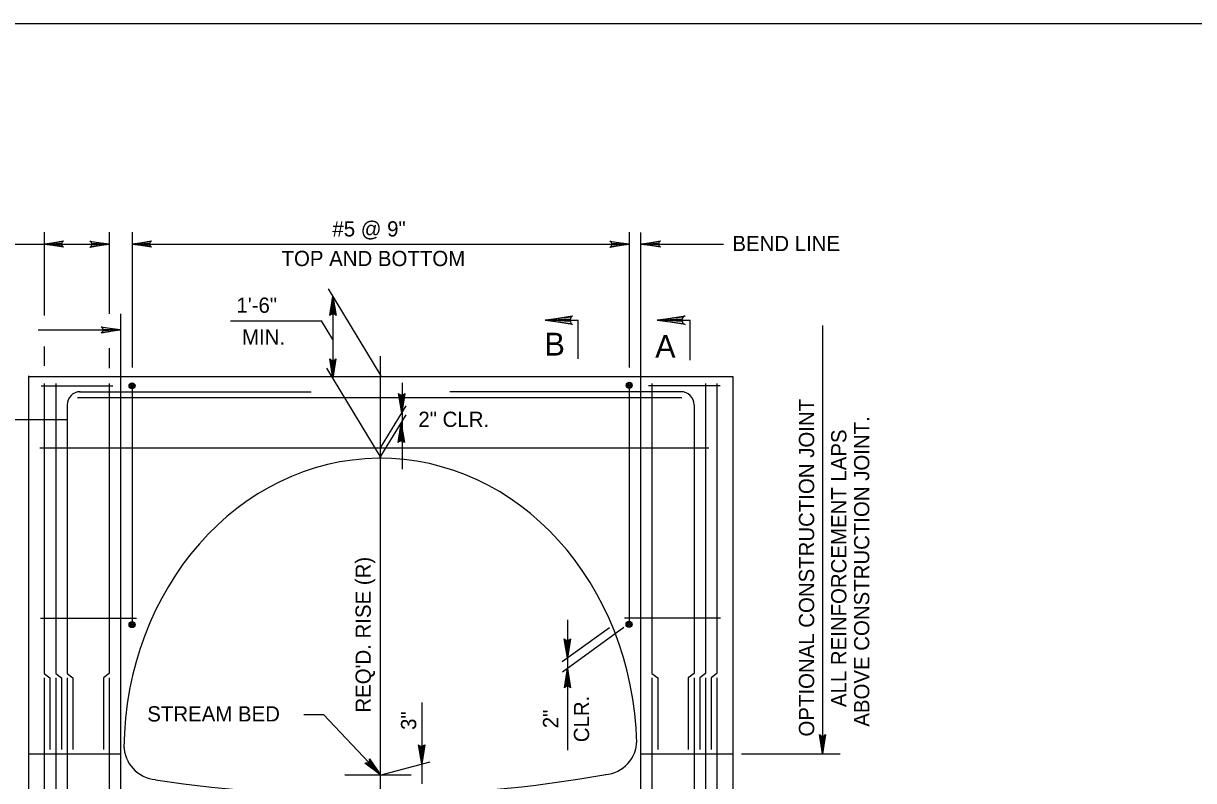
# Model space of a CAD drawing. Extents: x 639011 to 639866, y 298840 to 300028.
# Drawn here: x 639168.1 to 639398.1, y 299269.9 to 299418.8 of the extents above; entities that cross this region are included whole.
import ezdxf

# ---------------------------------------------------------------- set-up
doc = ezdxf.new("R2010")
doc.units = 0
doc.layers.add('2', color=7, linetype='Continuous')

msp = doc.modelspace()

# ---------------------------------------------------------------- linework, layer by layer
at = {"layer": '2'}
for p, q in [((639051.26, 299418.83), (639837.26, 299418.83)), ((639172.17, 299377.76), (639172.17, 299361.38)), ((639184.93, 299377.76), (639184.93, 299361.72)), ((639189.43, 299377.76), (639189.43, 299351.14)), ((639287.15, 299377.76), (639287.15, 299351.14)), ((639289.4, 299377.71), (639289.4, 299238.79)), ((639166.21, 299375.41), (639184.93, 299375.41)), ((639172.17, 299375.41), (639175.96, 299376.04)), ((639175.77, 299375.87), (639172.17, 299375.41)), ((639172.17, 299375.41), (639175.64, 299375.6)), ((639172.17, 299375.41), (639175.64, 299375.42)), ((639175.64, 299375.24), (639172.17, 299375.41)), ((639172.17, 299375.41), (639175.78, 299374.98)), ((639175.97, 299374.82), (639172.17, 299375.41)), ((639175.64, 299375.6), (639175.77, 299375.87)), ((639175.64, 299375.24), (639175.64, 299375.6)), ((639175.78, 299374.98), (639175.64, 299375.24)), ((639175.96, 299376.04), (639175.77, 299375.87)), ((639175.78, 299374.98), (639175.97, 299374.82)), ((639181.32, 299375.84), (639181.13, 299376)), ((639181.13, 299376), (639184.93, 299375.41)), ((639184.93, 299375.41), (639181.14, 299374.77)), ((639181.14, 299374.77), (639181.33, 299374.95)), ((639181.32, 299375.84), (639181.46, 299375.57)), ((639184.93, 299375.41), (639181.32, 299375.84)), ((639181.33, 299374.95), (639184.93, 299375.41)), ((639181.46, 299375.21), (639181.33, 299374.95)), ((639181.46, 299375.57), (639184.93, 299375.41)), ((639181.46, 299375.57), (639181.46, 299375.21)), ((639184.93, 299375.41), (639181.46, 299375.21)), ((639184.93, 299375.41), (639181.46, 299375.39)), ((639189.43, 299375.41), (639193.22, 299376.04)), ((639193.03, 299375.87), (639189.43, 299375.41)), ((639189.43, 299375.41), (639192.9, 299375.6)), ((639189.43, 299375.41), (639192.9, 299375.42)), ((639189.43, 299375.41), (639287.15, 299375.41)), ((639192.9, 299375.24), (639189.43, 299375.41)), ((639189.43, 299375.41), (639193.04, 299374.98)), ((639193.23, 299374.82), (639189.43, 299375.41)), ((639192.9, 299375.6), (639193.03, 299375.87)), ((639192.9, 299375.24), (639192.9, 299375.6)), ((639193.04, 299374.98), (639192.9, 299375.24)), ((639193.22, 299376.04), (639193.03, 299375.87)), ((639193.04, 299374.98), (639193.23, 299374.82)), ((639283.54, 299375.84), (639283.35, 299376)), ((639283.35, 299376), (639287.15, 299375.41)), ((639287.15, 299375.41), (639283.36, 299374.77)), ((639283.36, 299374.77), (639283.55, 299374.95)), ((639283.54, 299375.84), (639283.68, 299375.57)), ((639287.15, 299375.41), (639283.54, 299375.84)), ((639283.55, 299374.95), (639287.15, 299375.41)), ((639283.68, 299375.21), (639283.55, 299374.95)), ((639283.68, 299375.57), (639287.15, 299375.41)), ((639283.68, 299375.57), (639283.68, 299375.21)), ((639287.15, 299375.41), (639283.68, 299375.21)), ((639287.15, 299375.41), (639283.68, 299375.39)), ((639289.54, 299375.42), (639293.34, 299376.05)), ((639293.14, 299375.88), (639289.54, 299375.42)), ((639289.54, 299375.42), (639293.01, 299375.61)), ((639289.54, 299375.42), (639293.02, 299375.43)), ((639289.54, 299375.42), (639305.74, 299375.42)), ((639293.02, 299375.25), (639289.54, 299375.42)), ((639289.54, 299375.42), (639293.15, 299374.99)), ((639293.34, 299374.83), (639289.54, 299375.42)), ((639293.01, 299375.61), (639293.14, 299375.88)), ((639293.02, 299375.25), (639293.01, 299375.61)), ((639293.15, 299374.99), (639293.02, 299375.25)), ((639293.34, 299376.05), (639293.14, 299375.88)), ((639293.15, 299374.99), (639293.34, 299374.83)), ((639238.42, 299349.51), (639228.02, 299366.65)), ((639228.34, 299361.35), (639228.93, 299365.16)), ((639228.93, 299365.16), (639228.5, 299361.55)), ((639228.76, 299361.68), (639228.93, 299365.16)), ((639228.93, 299365.16), (639228.93, 299349.03)), ((639228.93, 299365.16), (639229.13, 299361.68)), ((639229.39, 299361.56), (639228.93, 299365.16)), ((639228.93, 299365.16), (639229.57, 299361.36)), ((639228.93, 299365.16), (639228.95, 299361.68)), ((639187.18, 299361.72), (639187.18, 299238.5)), ((639228.5, 299361.55), (639228.34, 299361.35)), ((639228.5, 299361.55), (639228.76, 299361.68)), ((639228.76, 299361.68), (639229.13, 299361.68)), ((639229.13, 299361.68), (639229.39, 299361.56)), ((639229.57, 299361.36), (639229.39, 299361.56)), ((639170.98, 299358.55), (639187.18, 299358.55)), ((639183.57, 299358.98), (639183.38, 299359.14)), ((639183.38, 299359.14), (639187.18, 299358.55)), ((639187.18, 299358.55), (639183.39, 299357.91)), ((639183.57, 299358.98), (639183.71, 299358.71)), ((639187.18, 299358.55), (639183.57, 299358.98)), ((639183.58, 299358.09), (639187.18, 299358.55)), ((639183.71, 299358.71), (639187.18, 299358.55)), ((639183.71, 299358.71), (639183.71, 299358.35)), ((639187.18, 299358.55), (639183.71, 299358.35)), ((639187.18, 299358.55), (639183.71, 299358.53)), ((639208.76, 299360.34), (639226.67, 299360.34)), ((639228.93, 299356.62), (639226.67, 299360.34)), ((639270.67, 299360.44), (639277.17, 299360.44)), ((639270.67, 299360.44), (639277.17, 299360.44)), ((639277.17, 299352.82), (639277.17, 299360.44)), ((639292.67, 299360.44), (639299.17, 299360.44)), ((639292.67, 299360.44), (639299.17, 299360.44)), ((639299.17, 299352.59), (639299.17, 299360.44)), ((639299.17, 299355.82), (639299.17, 299360.44)), ((639325.2, 299359.41), (639325.2, 299275.13)), ((639183.39, 299357.91), (639183.58, 299358.09)), ((639183.71, 299358.35), (639183.58, 299358.09)), ((639172.17, 299355.29), (639172.17, 299351.44)), ((639184.93, 299354.96), (639184.93, 299351.04)), ((639228.93, 299349.03), (639228.3, 299352.83)), ((639228.3, 299352.83), (639228.47, 299352.63)), ((639228.73, 299352.5), (639228.47, 299352.63)), ((639228.47, 299352.63), (639228.93, 299349.03)), ((639228.93, 299349.03), (639228.73, 299352.5)), ((639229.1, 299352.5), (639228.73, 299352.5)), ((639228.93, 299349.03), (639228.92, 299352.5)), ((639229.52, 299352.83), (639228.93, 299349.03)), ((639228.93, 299349.03), (639229.36, 299352.64)), ((639229.1, 299352.5), (639228.93, 299349.03)), ((639229.36, 299352.64), (639229.1, 299352.5)), ((639229.36, 299352.64), (639229.52, 299352.83)), ((639238.29, 299211.29), (639238.29, 299353.37)), ((639169.04, 299349.51), (639169.04, 299242.01)), ((639169.04, 299349.38), (639187.18, 299349.38)), ((639187.18, 299349.38), (639289.4, 299349.38)), ((639238.42, 299333.38), (639227.71, 299351.04)), ((639289.4, 299349.38), (639307.54, 299349.38)), ((639307.54, 299349.38), (639307.54, 299265.13)), ((639171.56, 299347.51), (639185.64, 299347.51)), ((639172.17, 299348), (639172.17, 299290.98)), ((639174.42, 299348), (639174.42, 299290.98)), ((639184.93, 299348.02), (639184.93, 299290.98)), ((639189.43, 299347.04), (639189.43, 299301.19)), ((639242.51, 299348.16), (639242.51, 299331.12)), ((639287.15, 299347.04), (639287.15, 299301.19)), ((639305.03, 299347.51), (639290.94, 299347.51)), ((639291.65, 299348.02), (639291.65, 299290.98)), ((639302.17, 299348), (639302.17, 299290.98)), ((639304.42, 299348), (639304.42, 299290.98)), ((639178.73, 299345.26), (639297.54, 299345.26)), ((639179.11, 299346.38), (639224.65, 299346.38)), ((639242.46, 299342.21), (639241.83, 299346)), ((639241.83, 299346), (639242, 299345.81)), ((639242.27, 299345.68), (639242, 299345.81)), ((639242, 299345.81), (639242.46, 299342.21)), ((639242.46, 299342.21), (639242.27, 299345.68)), ((639242.63, 299345.68), (639242.27, 299345.68)), ((639242.46, 299342.21), (639242.45, 299345.68)), ((639243.05, 299346.01), (639242.46, 299342.21)), ((639242.46, 299342.21), (639242.89, 299345.82)), ((639242.63, 299345.68), (639242.46, 299342.21)), ((639242.89, 299345.82), (639242.63, 299345.68)), ((639242.89, 299345.82), (639243.05, 299346.01)), ((639297.47, 299346.38), (639251.91, 299346.38)), ((639176.67, 299343.8), (639176.67, 299290.98)), ((639238.29, 299335.37), (639243.3, 299343.62)), ((639299.92, 299343.8), (639299.92, 299290.98)), ((639176.52, 299340.83), (639154.57, 299340.83)), ((639238.17, 299333.38), (639243.31, 299341.86)), ((639241.76, 299336.41), (639242.35, 299340.22)), ((639242.35, 299340.22), (639241.92, 299336.61)), ((639242.19, 299336.74), (639242.35, 299340.22)), ((639242.35, 299340.22), (639242.55, 299336.75)), ((639242.81, 299336.62), (639242.35, 299340.22)), ((639242.35, 299340.22), (639242.99, 299336.42)), ((639242.35, 299340.22), (639242.37, 299336.74)), ((639171.28, 299335.37), (639302.83, 299335.37)), ((639241.92, 299336.61), (639241.76, 299336.41)), ((639241.92, 299336.61), (639242.19, 299336.74)), ((639242.19, 299336.74), (639242.55, 299336.75)), ((639242.55, 299336.75), (639242.81, 299336.62)), ((639242.99, 299336.42), (639242.81, 299336.62)), ((639171.43, 299301.83), (639190.31, 299301.83)), ((639275.02, 299301.49), (639275.02, 299293.97)), ((639305.15, 299301.83), (639286.27, 299301.83)), ((639283.28, 299299.94), (639274.02, 299293.23)), ((639286.15, 299299.98), (639274.05, 299291.2)), ((639275.02, 299293.97), (639274.39, 299297.77)), ((639274.39, 299297.77), (639274.56, 299297.57)), ((639274.82, 299297.45), (639274.56, 299297.57)), ((639274.56, 299297.57), (639275.02, 299293.97)), ((639275.02, 299293.97), (639274.82, 299297.45)), ((639275.19, 299297.45), (639274.82, 299297.45)), ((639275.02, 299293.97), (639275, 299297.45)), ((639275.61, 299297.78), (639275.02, 299293.97)), ((639275.02, 299293.97), (639275.45, 299297.58)), ((639275.19, 299297.45), (639275.02, 299293.97)), ((639275.45, 299297.58), (639275.19, 299297.45)), ((639275.45, 299297.58), (639275.61, 299297.78)), ((639275.02, 299293.97), (639275.02, 299291.94)), ((639274.43, 299288.14), (639275.02, 299291.94)), ((639275.02, 299291.94), (639274.59, 299288.33)), ((639274.85, 299288.47), (639275.02, 299291.94)), ((639275.02, 299291.94), (639275.02, 299275.87)), ((639275.02, 299291.94), (639275.22, 299288.47)), ((639275.48, 299288.34), (639275.02, 299291.94)), ((639275.02, 299291.94), (639275.65, 299288.15)), ((639275.02, 299291.94), (639275.03, 299288.47)), ((639172.17, 299290.98), (639173.29, 299290.11)), ((639172.17, 299290.11), (639172.17, 299243.37)), ((639173.29, 299290.11), (639173.29, 299275.98)), ((639174.42, 299290.98), (639175.54, 299290.11)), ((639174.42, 299290.11), (639174.42, 299243.37)), ((639175.54, 299290.11), (639175.54, 299275.98)), ((639176.67, 299290.98), (639177.79, 299290.11)), ((639176.67, 299290.11), (639176.67, 299247.73)), ((639177.79, 299290.11), (639177.79, 299275.98)), ((639184.93, 299290.98), (639183.81, 299290.11)), ((639183.81, 299290.11), (639183.81, 299275.98)), ((639184.93, 299290.11), (639184.93, 299243.56)), ((639291.65, 299290.98), (639292.78, 299290.11)), ((639291.65, 299290.11), (639291.65, 299243.56)), ((639292.78, 299290.11), (639292.78, 299275.98)), ((639299.92, 299290.98), (639298.79, 299290.11)), ((639298.79, 299290.11), (639298.79, 299275.98)), ((639299.92, 299290.11), (639299.92, 299247.72)), ((639302.17, 299290.98), (639301.04, 299290.11)), ((639301.04, 299290.11), (639301.04, 299275.98)), ((639302.17, 299290.11), (639302.17, 299243.37)), ((639304.42, 299290.98), (639303.29, 299290.11)), ((639303.29, 299290.11), (639303.29, 299275.98)), ((639304.42, 299290.11), (639304.42, 299243.37)), ((639274.59, 299288.33), (639274.43, 299288.14)), ((639274.59, 299288.33), (639274.85, 299288.47)), ((639274.85, 299288.47), (639275.22, 299288.47)), ((639275.22, 299288.47), (639275.48, 299288.34)), ((639275.65, 299288.15), (639275.48, 299288.34)), ((639246.38, 299285.23), (639246.38, 299273.15)), ((639223.17, 299282.88), (639227.04, 299282.88)), ((639227.04, 299282.88), (639238.29, 299271.01)), ((639325.2, 299275.13), (639324.57, 299278.93)), ((639324.57, 299278.93), (639324.75, 299278.73)), ((639325.01, 299278.6), (639324.75, 299278.73)), ((639324.75, 299278.73), (639325.2, 299275.13)), ((639325.37, 299278.61), (639325.01, 299278.6)), ((639325.2, 299275.13), (639325.01, 299278.6)), ((639325.2, 299275.13), (639325.19, 299278.6)), ((639325.79, 299278.93), (639325.2, 299275.13)), ((639325.2, 299275.13), (639325.63, 299278.74)), ((639325.37, 299278.61), (639325.2, 299275.13)), ((639325.63, 299278.74), (639325.37, 299278.61)), ((639325.63, 299278.74), (639325.79, 299278.93)), ((639246.38, 299273.15), (639245.75, 299276.94)), ((639245.75, 299276.94), (639245.92, 299276.74)), ((639246.18, 299276.62), (639245.92, 299276.74)), ((639245.92, 299276.74), (639246.38, 299273.15)), ((639246.38, 299273.15), (639246.18, 299276.62)), ((639246.55, 299276.62), (639246.18, 299276.62)), ((639246.38, 299273.15), (639246.37, 299276.62)), ((639246.97, 299276.95), (639246.38, 299273.15)), ((639246.38, 299273.15), (639246.81, 299276.76)), ((639246.55, 299276.62), (639246.38, 299273.15)), ((639246.81, 299276.76), (639246.55, 299276.62)), ((639246.81, 299276.76), (639246.97, 299276.95)), ((639169.07, 299275.13), (639187.21, 299275.13)), ((639238.29, 299271.01), (639235.22, 299273.33)), ((639235.22, 299273.33), (639235.48, 299273.3)), ((639235.76, 299273.39), (639235.48, 299273.3)), ((639235.48, 299273.3), (639238.29, 299271.01)), ((639236.02, 299273.64), (639235.76, 299273.39)), ((639238.29, 299271.01), (639235.76, 299273.39)), ((639238.29, 299271.01), (639235.89, 299273.52)), ((639236.12, 299273.92), (639236.02, 299273.64)), ((639236.02, 299273.64), (639238.29, 299271.01)), ((639236.12, 299273.92), (639236.11, 299274.17)), ((639236.11, 299274.17), (639238.29, 299271.01)), ((639238.29, 299271.01), (639236.12, 299273.92)), ((639238.42, 299271.01), (639248.01, 299273.58)), ((639289.31, 299275.13), (639307.6, 299275.13)), ((639309.28, 299275.13), (639328.62, 299275.13)), ((639231.29, 299271.01), (639244.29, 299271.01)), ((639246.38, 299273.15), (639246.38, 299269.24))]:
    msp.add_line(p, q, dxfattribs=at)
for points in [[(639275.79, 299359.82), (639275.67, 299360.19), (639270.67, 299360.44), (639275.79, 299359.82), (639276.04, 299359.57), (639270.67, 299360.44), (639275.67, 299360.69), (639275.79, 299361.07), (639270.67, 299360.44), (639276.04, 299361.32), (639275.79, 299361.07)], [(639275.79, 299359.82), (639275.67, 299360.19), (639270.67, 299360.44), (639275.79, 299359.82), (639276.04, 299359.57), (639270.67, 299360.44), (639275.67, 299360.69), (639275.79, 299361.07), (639270.67, 299360.44), (639276.04, 299361.32), (639275.79, 299361.07)], [(639297.79, 299359.82), (639297.67, 299360.19), (639292.67, 299360.44), (639297.79, 299359.82), (639298.17, 299359.57), (639292.67, 299360.44), (639297.67, 299360.69), (639297.79, 299361.07), (639292.67, 299360.44), (639298.17, 299361.32), (639297.79, 299361.07)], [(639297.79, 299359.82), (639297.67, 299360.19), (639292.67, 299360.44), (639297.79, 299359.82), (639298.17, 299359.57), (639292.67, 299360.44), (639297.67, 299360.69), (639297.79, 299361.07), (639292.67, 299360.44), (639298.17, 299361.32), (639297.79, 299361.07)]]:
    msp.add_lwpolyline(points, dxfattribs=at)
for centre, radius in [((639189.43, 299347.54), 0.596), ((639189.43, 299347.54), 0.425), ((639189.43, 299347.54), 0.425), ((639189.43, 299347.54), 0.233), ((639189.43, 299347.54), 0.233), ((639189.43, 299347.54), 0.117), ((639189.43, 299347.54), 0.117), ((639189.43, 299347.54), 0.0503), ((639189.43, 299347.54), 0.0503), ((639287.17, 299347.63), 0.596), ((639287.17, 299347.63), 0.425), ((639287.17, 299347.63), 0.425), ((639287.17, 299347.63), 0.233), ((639287.17, 299347.63), 0.233), ((639287.17, 299347.63), 0.117), ((639287.17, 299347.63), 0.117), ((639287.17, 299347.63), 0.0503), ((639287.17, 299347.63), 0.0503), ((639189.43, 299300.57), 0.596), ((639189.43, 299300.57), 0.425), ((639189.43, 299300.57), 0.425), ((639287.15, 299300.63), 0.596), ((639287.15, 299300.63), 0.425), ((639287.15, 299300.63), 0.425), ((639287.15, 299300.63), 0.233), ((639287.15, 299300.63), 0.233), ((639189.43, 299300.57), 0.233), ((639189.43, 299300.57), 0.233), ((639189.43, 299300.57), 0.117), ((639189.43, 299300.57), 0.117), ((639189.43, 299300.57), 0.0503), ((639189.43, 299300.57), 0.0503), ((639287.15, 299300.63), 0.117), ((639287.15, 299300.63), 0.117), ((639287.15, 299300.63), 0.0503), ((639287.15, 299300.63), 0.0503)]:
    msp.add_circle(centre, radius, dxfattribs=at)
for centre, radius, start, end in [((639179.25, 299343.8), 2.58, 90, 180), ((639297.34, 299343.8), 2.58, 0, 90), ((639194.58, 299276.82), 6.74, 180.2331, 265.3705), ((639281.93, 299277.8), 6.74, 274.6295, 359.7669), ((639235.19, 299539.88), 272.95, 261.3243, 279.9929)]:
    msp.add_arc(centre, radius, start, end, dxfattribs=at)
msp.add_ellipse((639238.26, 299275.66), major_axis=(0, 57.62), ratio=0.87514, start_param=4.740498, end_param=7.842251, dxfattribs=at)

# ---------------------------------------------------------------- texts
for s, height, p in [('#5 @ 9"', 3, (639228.82, 299376.91)), ('BEND LINE', 3, (639307.46, 299374.04)), ('TOP AND BOTTOM', 3, (639218.82, 299371.09)), ('1\'-6"', 3, (639209.95, 299361.9)), ('MIN.', 3, (639211.05, 299355.63)), ('B', 4.5, (639270.51, 299353.49)), ('A', 4.5, (639292.28, 299353.05)), ('2" CLR.', 3, (639245.72, 299339.45)), ('STREAM BED', 3, (639192.42, 299281.51))]:
    msp.add_text(s, height=height, dxfattribs=at).set_placement(p)
for s, p in [('OPTIONAL CONSTRUCTION JOINT', (639323.54, 299278.55)), ('ABOVE CONSTRUCTION JOINT.', (639334.38, 299280.49)), ('ALL REINFORCEMENT LAPS', (639329.88, 299284.34)), ("REQ'D. RISE (R)", (639236.37, 299283.26)), ('CLR.', (639279.29, 299277.44)), ('3"', (639245.3, 299279.85)), ('2"', (639273.21, 299280.19))]:
    msp.add_text(s, height=3, rotation=90, dxfattribs=at).set_placement(p)

doc.saveas('drawing.dxf')
